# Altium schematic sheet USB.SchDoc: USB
size A4; Date: Not used; ApprovedBy: Not used; CheckedBy: Not used; Author: Not used; CompanyName: STMicroelectronics; DrawnBy: Not used; Engineer: Not used; Organization: Not used; Address1: Not used; Address2: Not used; Address3: Not used; Address4: Not used; DocumentNumber: 7; Revision: Not used; SheetNumber: 7; SheetTotal: 9
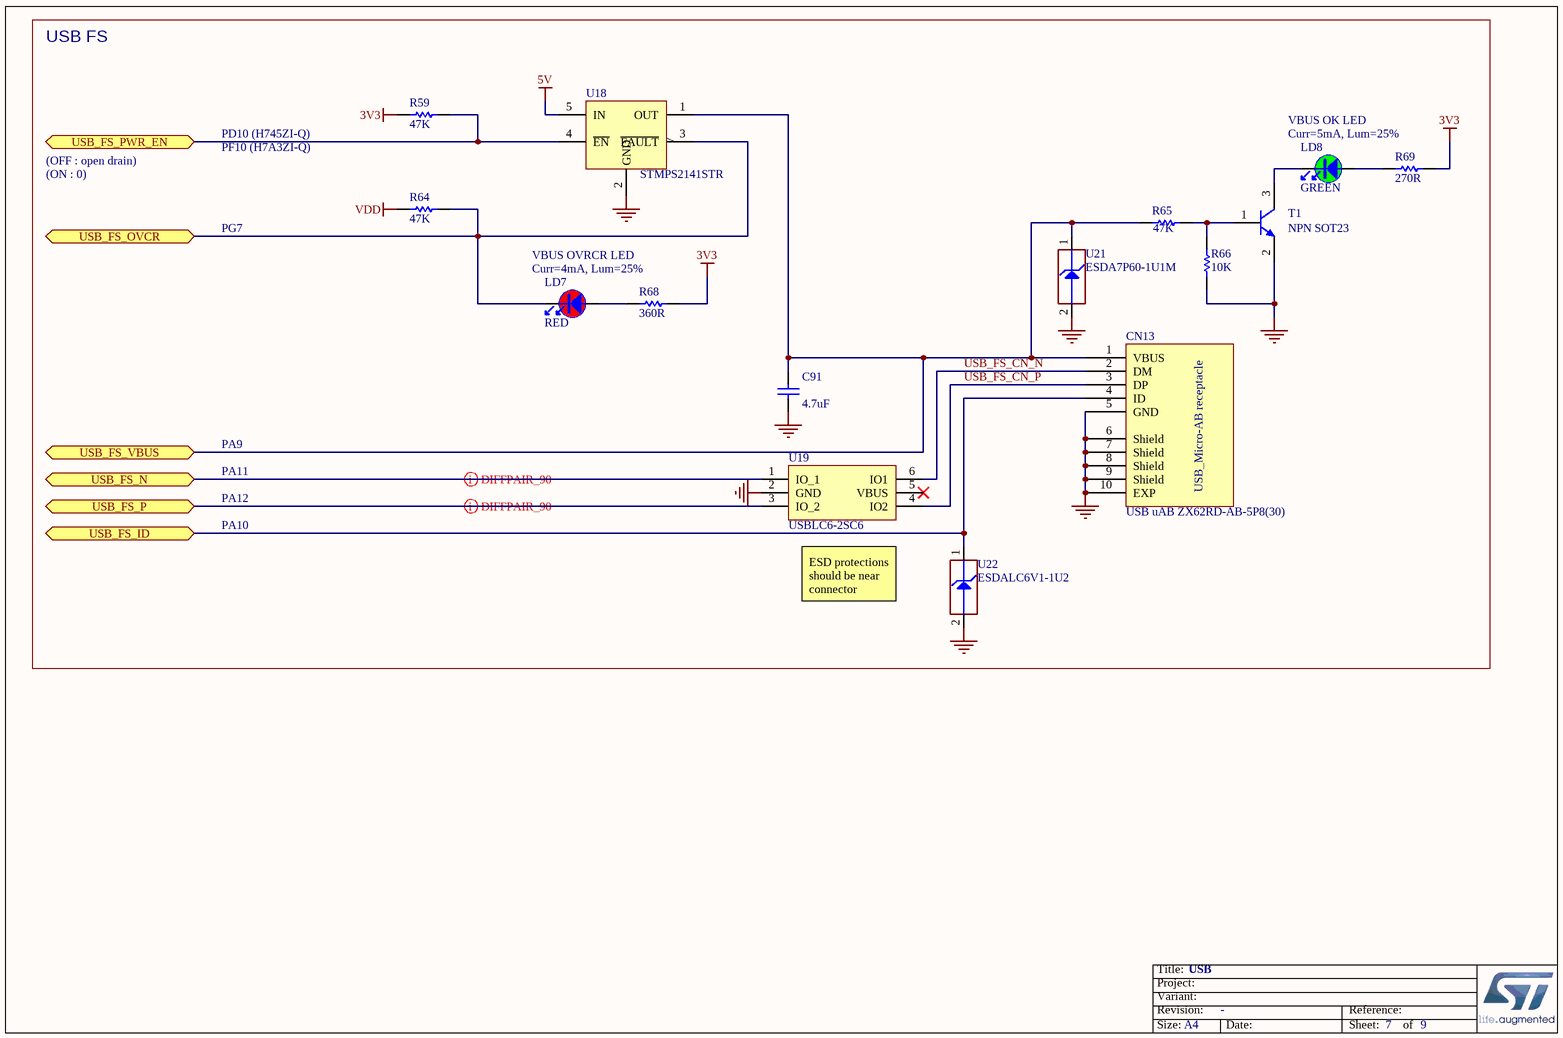
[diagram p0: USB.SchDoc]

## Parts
C91  value 4.7uF  [C0603]  (hidden comment: Capacitor)
CN13  value USB uAB ZX62RD-AB-5P8(30)  [CON_USBMICROAB_MOLEX_47590-0001_H3]  (hidden comment: USB_uAB_47590.0001)
LD7  value RED  [LED_0603_VISHAY_VLMS1300-GS08_RED_1A2K_H0P8]  (hidden comment: LED_red)
LD8  value GREEN  [LED_0603_OSRAM_LG-Q396-PS-35_GREEN_1A2K_H0P4]  (hidden comment: LED_green)
R59  value 47K  [R0402]  (hidden comment: Resistor)
R64  value 47K  [R0402]  (hidden comment: Resistor)
R65  value 47K  [R0402]  (hidden comment: Resistor)
R66  value 10K  [R0402]  (hidden comment: Resistor)
R68  value 360R  [R0402]  (hidden comment: Resistor)
R69  value 270R  [R0402]  (hidden comment: Resistor)
T1  value NPN SOT23  [NPN_SOT23]  (hidden comment: 9013-SOT23)
U18  STMPS2141STR  [MOS_SOT23-5L]
U19  USBLC6-2SC6  [ESD_SOT23-6L]
U21  value ESDA7P60-1U1M  [ESD_QFN2_1P6X1_P125]  (hidden comment: ESD-TRANSIL)
U22  value ESDALC6V1-1U2  [ESD_ST0201]  (hidden comment: ESD-TRANSIL)

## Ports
USB_FS_ID, USB_FS_N, USB_FS_OVCR, USB_FS_P, USB_FS_PWR_EN, USB_FS_VBUS

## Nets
3V3: R59.2 R68.2 R69.2
5V: U18.5(IN)
GND: C91.1 CN13.5(GND) CN13.6(Shield) CN13.7(Shield) CN13.8(Shield) CN13.9(Shield) CN13.10(EXP) R66.1 T1.2(E) U18.2(GND) U19.2(GND) U21.2(GND) U22.2(GND)
VDD: R64.2
USB_FS_CN_N: CN13.2(DM) U19.6(IO1)
USB_FS_CN_P: CN13.3(DP) U19.4(IO2)
USB_FS_ID: CN13.4(ID) U22.1(IO1) ; port USB_FS_ID
USB_FS_N: U19.1(IO_1) ; port USB_FS_N
USB_FS_OVCR: LD7.2 R64.1 U18.3(~{FAULT}) ; port USB_FS_OVCR
USB_FS_P: U19.3(IO_2) ; port USB_FS_P
USB_FS_PWR_EN: R59.1 U18.4(~{EN}) ; port USB_FS_PWR_EN
USB_FS_VBUS: C91.2 CN13.1(VBUS) R65.1 U18.1(OUT) U21.1(IO1) ; port USB_FS_VBUS
NetLD7_1: LD7.1 R68.1
NetLD8_1: LD8.1 R69.1
NetLD8_2: LD8.2 T1.3(C)
NetR65_2: R65.2 R66.2 T1.1(B)

Not connected (* = marked no-connect by the designer): U19 5(VBUS)*

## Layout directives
differential pair: USB_FS_N, USB_FS_P

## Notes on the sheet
- USB FS
- (OFF : open drain)
- (ON : 0)
- PD10 (H745ZI-Q)
- PF10 (H7A3ZI-Q)
- VBUS OK LED
- Curr=5mA, Lum=25%
- PG7
- VBUS OVRCR LED
- Curr=4mA, Lum=25%
- PA9
- PA11
- PA12
- PA10
- (near U19) ESD protections should be near connector

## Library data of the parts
C91 = MCD-00009: Capacitor, MLCC, 4.7uF, 16V, X5R, 10%, 0603, T=0.8mm; Manufacturer_Part_Number: CC0603KRX5R7BB475; Manufacturer: YAGEO; Provided_By: SUBCO; ECCN_US: EAR99; ECCN_EU: NEC
CN13 = MCD-00661: USB-MICRO-AB Receptacle, RA, SMT + DIP, Standard, Top Mount, USB certified (symbol & footprint compatible with MCD-00022); Part_Type: Connector; Manufacturer_Part_Number: ZX62RD-AB-5P8(30); Manufacturer: HIROSE; Provided_By: SUBCO
LD7 = MCD-00587: LED Red, 0603 SMD, 2V Forward Voltage; Part_Type: Display; Manufacturer_Part_Number: VLMS1300-GS08; Manufacturer: VISHAY; Alternate_Manufacturer_Part_Number: LS Q976-NR-1; Alternate_Manufacturer: OSRAM OPTO SEMICONDUCTORS; Provided_By: SUBCO
LD8 = MCD-00588: LED Green, 0603 SMD, Forward Voltage Typ=2V, Max=2.5V; Part_Type: Display; Manufacturer_Part_Number: LG Q396-PS-35; Manufacturer: OSRAM OPTO SEMICONDUCTORS; Alternate_Manufacturer_Part_Number: VLMTG1300-GS08; Alternate_Manufacturer: VISHAY SEMICONDUCTOR OPTO DIVISION; Provided_By: SUBCO
R59 R64 R65 = MCD-00063: Resistor,47K,0402,1%,1/16W; Manufacturer_Part_Number: RC0402FR-0747KL; Manufacturer: YAGEO; Provided_By: SUBCO; ECCN_US: EAR99; ECCN_EU: NEC
R66 = MCD-00053: Resistor,10K,0402,1%,1/16W; Manufacturer_Part_Number: RC0402FR-0710KL; Manufacturer: YAGEO; Provided_By: SUBCO; ECCN_US: EAR99; ECCN_EU: NEC
R68 = MCD-00461: Resistor,360R,0402,1%,1/16W; Manufacturer_Part_Number: RC0402FR-07360RL; Manufacturer: YAGEO; Provided_By: SUBCO; ECCN_US: EAR99; ECCN_EU: NEC
R69 = MCD-00441: Resistor,270R,0402,1%,1/16W; Manufacturer_Part_Number: RC0402FR-07270RL; Manufacturer: YAGEO; Provided_By: SUBCO; ECCN_US: EAR99; ECCN_EU: NEC
T1 = MCD-00073: NPN Bipolar Transistor; Manufacturer_Part_Number: BSR14; Manufacturer: ON SEMICONDUCTOR; Part_Type: IC; Alternate_Manufacturer_Part_Number: MMBT2222LT1G / MMBT2222ALT1G / MMBT2222ALT3G; Provided_By: SUBCO; ECCN_US: EAR99; ECCN_EU: NEC
U18 = MCD-00083: Enhanced single channel power switches with active low enable pin; Part_Type: IC; Manufacturer: STMICROELECTRONICS; Alternate_Manufacturer_Part_Number: TPS2041C; Alternate_Manufacturer: TEXAS INSTRUMENTS; BMS_Part_Number: 9159003; Provided_By: SUBCO with ST control; ECCN_US: EAR99; ECCN_EU: NEC
U19 = MCD-00163: Very low capacitance ESD protection; Part_Type: IC; Manufacturer: STMICROELECTRONICS; BMS_Part_Number: 9151075; Provided_By: SUBCO with ST control; ECCN_US: EAR99; ECCN_EU: NEC
U21 = MCD-00251: High power transient voltage suppressor, 7V breakdown; Part_Type: Diode; Manufacturer: STMICROELECTRONICS; BMS_Part_Number: 9179042; Provided_By: SUBCO with ST control; ECCN_US: EAR99; ECCN_EU: NEC
U22 = MCD-00170: ESD protection 6V1; Part_Type: Diode; Manufacturer: STMICROELECTRONICS; BMS_Part_Number: 9151132; Provided_By: SUBCO with ST control; ECCN_US: EAR99; ECCN_EU: NEC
